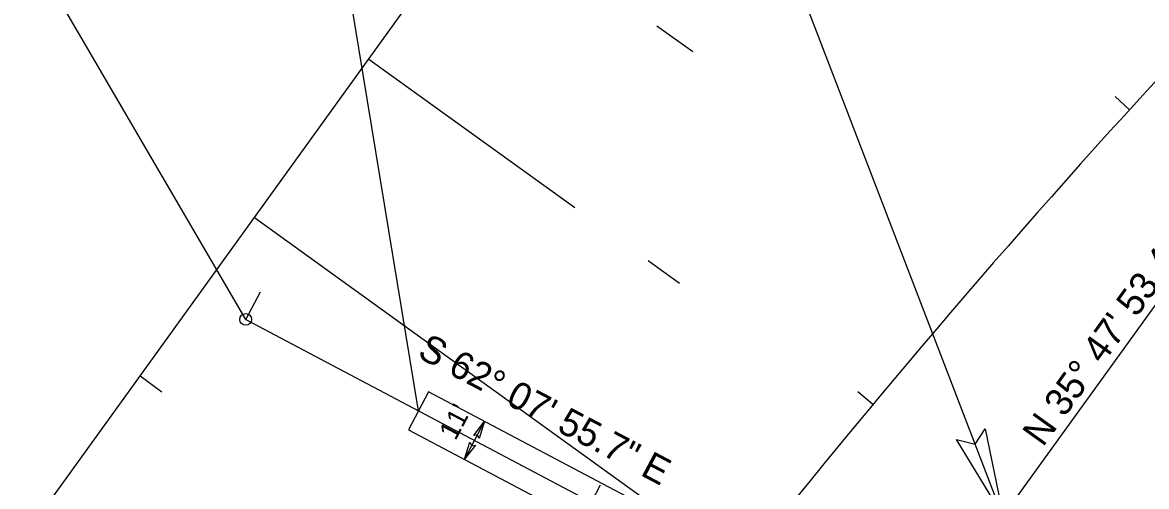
# Model space of a CAD drawing. Extents: x 2189281 to 2191267, y 386656 to 389012.
# Drawn here: x 2190273 to 2190560.4, y 388159.5 to 388278.3 of the extents above; entities that cross this region are included whole.
import ezdxf

# ---------------------------------------------------------------- set-up
doc = ezdxf.new("R2010")
doc.units = 0
for name, color, linetype in [('Prop Dimension', 7, 'Continuous'), ('Prop Dimension Text', 7, 'Continuous'), ('Prop DSN Text', 7, 'Continuous'), ('Prop EOT', 7, 'Continuous'), ('Prop Horizontal Alignment', 7, 'Continuous'), ('Prop Horizontal Alignment Direction Label', 7, 'Continuous'), ('Prop Horizontal Alignment Station Label', 7, 'Continuous'), ('Prop Horizontal Alignment Tick Large', 7, 'Continuous'), ('Prop Horizontal Alignment Tick Small', 7, 'Continuous'), ('Prop Terminator CELL', 7, 'Continuous'), ('Scratch_Level_5', 7, 'Continuous')]:
    doc.layers.add(name, color=color, linetype=linetype)

msp = doc.modelspace()

# ---------------------------------------------------------------- linework, layer by layer
at = {"layer": 'Prop Dimension'}
msp.add_line((2190391.14, 388176.22), (2190386, 388166.5), dxfattribs=at)
at = {"layer": 'Prop DSN Text'}
for p, q in [((2190523.75, 388151.95), (2190443.96, 388359.41)), ((2190374.26, 388178.93), (2190353.32, 388306.02))]:
    msp.add_line(p, q, dxfattribs=at)
at = {"layer": 'Prop EOT'}
for p, q in [((2190376.83, 388183.79), (2190371.69, 388174.06)), ((2190466.8, 388136.22), (2190376.83, 388183.79)), ((2190371.69, 388174.06), (2190452.14, 388131.53))]:
    msp.add_line(p, q, dxfattribs=at)
at = {"layer": 'Prop Horizontal Alignment'}
for p, q in [((2189529.37, 386773.11), (2190699.23, 388395.27)), ((2190330.06, 388202.3), (2190496.57, 388114.25))]:
    msp.add_line(p, q, dxfattribs=at)
msp.add_arc((2192257.95, 386708.79), 2300, 135.25499, 144.20184, dxfattribs=at)
at = {"layer": 'Prop Horizontal Alignment Station Label'}
msp.add_lwpolyline([(2190330.06, 388202.3), (2190276.32, 388294.58), (2190346.2, 388390.82)], dxfattribs=at)
msp.add_circle((2190330.06, 388202.3), 1.5, dxfattribs=at)
at = {"layer": 'Prop Horizontal Alignment Tick Large'}
msp.add_line((2190330.06, 388202.3), (2190333.8, 388209.37), dxfattribs=at)
at = {"layer": 'Prop Horizontal Alignment Tick Small'}
for p, q in [((2190556.12, 388255.97), (2190552.42, 388259.33)), ((2190490.48, 388180.54), (2190486.64, 388183.74)), ((2190418.46, 388155.55), (2190420.8, 388159.97))]:
    msp.add_line(p, q, dxfattribs=at)
at = {"layer": 'Prop Terminator CELL'}
for points in [[(2190388.36, 388172.61), (2190391.14, 388176.22), (2190389.74, 388171.85), (2190389.3, 388172.73)], [(2190388.36, 388172.61), (2190391.14, 388176.22), (2190389.74, 388171.85), (2190389.3, 388172.73)], [(2190519.19, 388174.32), (2190523.75, 388151.95), (2190511.81, 388171.58), (2190516.58, 388170.35)], [(2190388.79, 388170.11), (2190386, 388166.5), (2190387.41, 388170.87), (2190387.85, 388169.99)]]:
    msp.add_lwpolyline(points, close=True, dxfattribs=at)
at = {"layer": 'Scratch_Level_5'}
for p, q in [((2189367.15, 386890.09), (2190537.02, 388512.26)), ((2190435.21, 388277.45), (2190444.4, 388270.82)), ((2190361.54, 388268.93), (2190414.19, 388230.96)), ((2190332.29, 388228.38), (2190604.85, 388031.82)), ((2190433.02, 388217.38), (2190441.03, 388211.61)), ((2190303.05, 388187.83), (2190308.64, 388183.79))]:
    msp.add_line(p, q, dxfattribs=at)

# ---------------------------------------------------------------- texts
at = {"layer": 'Prop Dimension Text'}
msp.add_text("11'", height=5, rotation=62.1321, dxfattribs=at).set_placement((2190383.7, 388171.1))
at = {"layer": 'Prop Horizontal Alignment Direction Label'}
for s, rotation, p in [('N 35%%d 47\' 53.4" E', 54.2018, (2190533.95, 388169.44)), ('S 62%%d 07\' 55.7" E', 332.1321, (2190373.66, 388192.75))]:
    msp.add_text(s, height=7, rotation=rotation, dxfattribs=at).set_placement(p)

doc.saveas('drawing.dxf')
